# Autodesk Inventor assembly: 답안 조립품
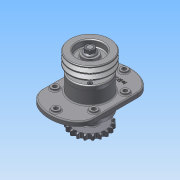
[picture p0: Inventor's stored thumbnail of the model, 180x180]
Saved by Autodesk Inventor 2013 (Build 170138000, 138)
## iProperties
Created: 2015-02
Part Number: 답안 조립품
Document SubType Name: Assembly
Designer: Administrator
Author: Administrator
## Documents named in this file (12)
- C:\Documents and Settings\Administrator\바탕 화면\450208V1017\답안 조립품.iam
- C:\Documents and Settings\Administrator\바탕 화면\450208V1017\1-본체.ipt
- C:\Documents and Settings\Administrator\바탕 화면\450208V1017\3-축.ipt
- C:\Documents and Settings\Administrator\바탕 화면\450208V1017\6-베어링 6206.ipt
- C:\Documents and Settings\Administrator\바탕 화면\450208V1017\7-부시.ipt
- C:\Documents and Settings\Administrator\바탕 화면\450208V1017\8-오일실 30x42.ipt
- C:\Documents and Settings\Administrator\바탕 화면\450208V1017\2-커버.ipt
- C:\Documents and Settings\Administrator\바탕 화면\450208V1017\10-M6.ipt
- C:\Documents and Settings\Administrator\바탕 화면\450208V1017\11-키 6x6.ipt
- C:\Documents and Settings\Administrator\바탕 화면\450208V1017\5-체인 스프로킷.ipt
- C:\Documents and Settings\Administrator\바탕 화면\450208V1017\4-V벨트풀리.ipt
- C:\Documents and Settings\Administrator\바탕 화면\450208V1017\9-M16-너트.ipt
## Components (23 placed, 11 different names)
1. 1-본체:1
2. 3-축:1 — 각도:1, 각도:3, 각도:5, 각도:6
3. 6-베어링 6206:1
4. 7-부시:1
5. 6-베어링 6206:2
6. 8-8-오일실 30x42:1
7. 2-커버:1
8. 8-8-오일실 30x42:2
9. 2-커버:2
10. 11-키 6x6:1 — 각도:1, 각도:2
11. 11-키 6x6:2 — 각도:3, 각도:4
12. 5-체인 스프로킷:1 — 각도:2
13. 4-V벨트풀리:1 — 각도:4
14. 9-M16 너트:1 — 각도:5
15. 9-M16 너트:2 — 각도:6
16. 10-M6:2
17. 10-M6:3
18. 10-M6:4
19. 10-M6:5
20. 10-M6:1
21. 10-M6:6
22. 10-M6:7
23. 10-M6:8
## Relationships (6: Angle 6)
- 각도:1 [Angle]: 3-축:1 ↔ 11-키 6x6:1
- 각도:2 [Angle]: 11-키 6x6:1 ↔ 5-체인 스프로킷:1
- 각도:3 [Angle]: 3-축:1 ↔ 11-키 6x6:2
- 각도:4 [Angle]: 11-키 6x6:2 ↔ 4-V벨트풀리:1
- 각도:5 [Angle]: 3-축:1 ↔ 9-M16 너트:1
- 각도:6 [Angle]: 3-축:1 ↔ 9-M16 너트:2
